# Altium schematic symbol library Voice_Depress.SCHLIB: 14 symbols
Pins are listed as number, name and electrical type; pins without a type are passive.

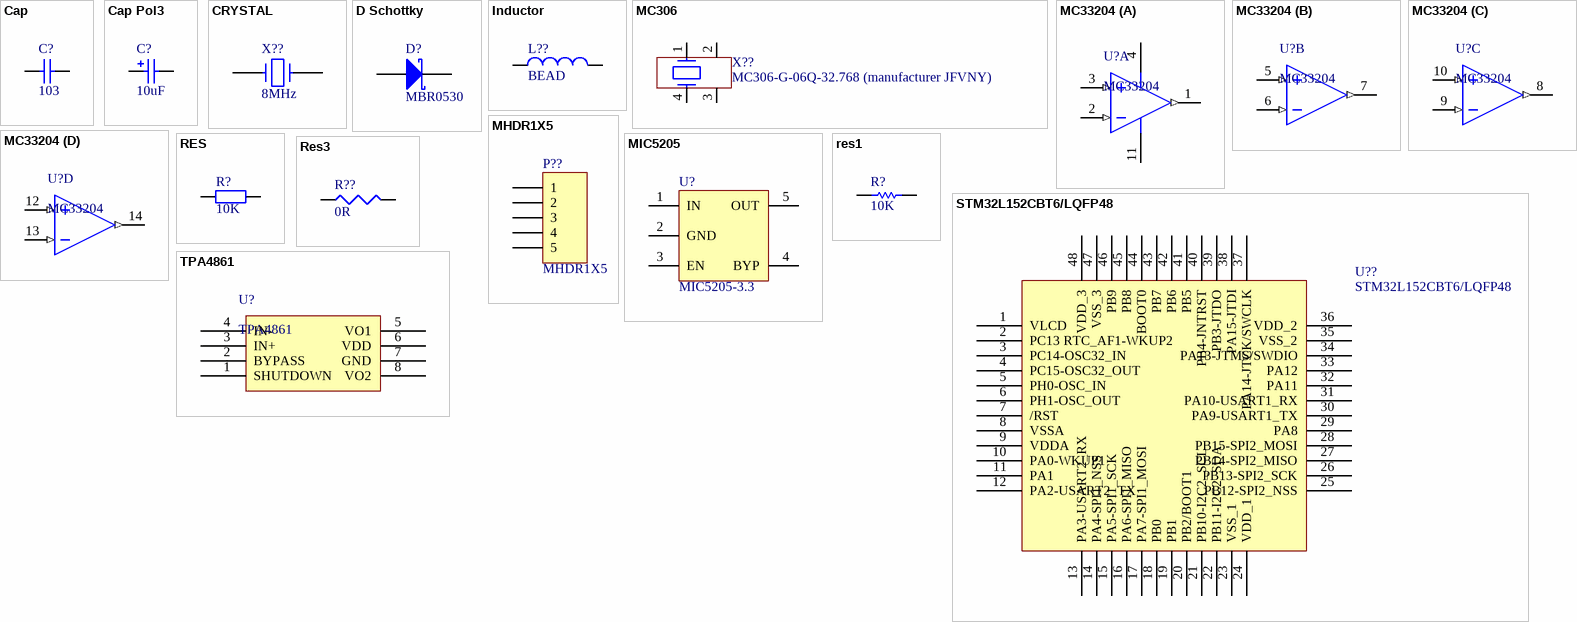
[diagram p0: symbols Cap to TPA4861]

## Cap
designator C?, comment 103
Capacitor
footprint RAD-0.3 (Capacitor; 2 Leads)
footprint CAPR2.54-5.1x3.2 (Capacitor, Ceramic, Thru-Hole, Dipped Radial; Body 5.1 x 3.2 mm (WxT) Pin Spacing 2.54 mm (typ))
footprint CAPR5.08-7.8x3.2 (Capacitor, Ceramic, Thru-Hole, Dipped Radial; Body 7.8 x 3.2 mm (WxT) Pin Spacing 5.08 mm (typ))
simulation model CAP (Capacitor)
signal-integrity model Cap
footprint CR2012-0805
footprint 2012[0805]
footprint CR1608-0603
footprint 1608[0603] (Chip Capacitor; Body 1.6 x 0.8 mm (LxW typ))
footprint R0603
footprint C0603
pins: 1, 2

## Cap Pol3
designator C?, comment 10uF
Polarized Capacitor (Surface Mount); Value: 100pF
simulation model CAP (Capacitor)
footprint 7227
footprint 贴片电容器47u/16V
footprint 3225[1210] (Chip Resistor; Body 3.2 x 2.5 mm (LxW typ))
footprint 6-0805 (Chip Resistor; Body 2.0 x 1.3 mm (LxW typ))
footprint [1608]0603
footprint 6-0805 (Chip Resistor; Body 2.0 x 1.3 mm (LxW typ))
pins: 1, 2
1 alternate drawing of the same symbol

## CRYSTAL
designator X??, comment 8MHz
Crystal
footprint XTAL_socket
pins: 1, 2
2 alternate drawings of the same symbol

## D Schottky
designator D?, comment MBR0530
Schottky Diode
footprint 3216[1206] (Chip Resistor; Body 3.2 x 1.6 mm (LxW typ))
simulation model SKYDIODE (Diode)
signal-integrity model D Schottky
footprint 1608[0603] (Chip Capacitor; Body 1.6 x 0.8 mm (LxW typ))
pins: 1 A, 2 K

## Inductor
designator L??, comment BEAD
Inductor; Code_IEC: 1005; Value: 10mH
footprint 0402-A (Chip Inductor; Body 1 x 0.5 mm (LxW typ))
footprint L0603 (Chip Inductor; Body 1.6 x 0.8 mm (LxW typ))
footprint 2012_Chip (2012 Chip; Chip Inductor; Body 2.0 x 1.2 mm (LxW typ))
footprint 2029 (Chip Inductor; Body 2 x 1.2 mm (LxW typ))
footprint 3261 (3216 Chip; Chip Inductor; Body 3.2 x 1.6 mm (LxW typ))
footprint 4564_Chip (4564 Chip; Chip Inductor; Body 4.5 x 6.4 mm (LxW typ))
simulation model INDUCTOR (Inductor)
signal-integrity model Inductor
pins: 1, 2

## MC306
designator X??, comment MC306-G-06Q-32.768 (manufacturer JFVNY)
footprint SM8 (Footprint not found)
footprint 32.768K-MC146 (XTAL-32.768K)
pins: 1, 2, 3, 4

## MC33204
designator U?
part A pins: 1 OUT1 (out), 2 IN1- (in), 3 IN1+ (in), 4 V+ (power), 11 V- (power)
part B pins: 5 IN1+ (in), 6 IN1- (in), 7 OUT1 (out)
part C pins: 8 OUT1 (out), 9 IN1- (in), 10 IN1+ (in)
part D pins: 12 IN1+ (in), 13 IN1- (in), 14 OUT1 (out)

## MHDR1X5
designator P??
Header, 5-Pin
footprint MHDR1X5 (Connector; Header; 5 Position)
signal-integrity model Connector
pins: 1, 2, 3, 4, 5

## MIC5205
designator U?, comment MIC5205-3.3
800mA Low Dropout Positive Regulator Fixed 2.85V,3V,3.3V and 5V; PackageDocument: revC
footprint SOT23-5 (SOT-23/SC-74A; 5 Leads; Body 3 x 3 mm, inc. leads (LxW max))
footprint DSO-G3 (SOT-223/SC-73; 4 Leads; Body 6.7 x 7.3 mm, inc. leads (LxW max))
footprint SOT23-5 (SOT-23/SC-74A; 5 Leads; Body 3 x 3 mm, inc. leads (LxW max))
footprint SOT23-5 (SOT-23/SC-74A; 5 Leads; Body 3 x 3 mm, inc. leads (LxW max))
pins: 1 IN (power), 2 GND (power), 3 EN (power), 4 BYP (power), 5 OUT (power)

## RES
designator R?, comment 10K
footprint R-0603
footprint R-0805
footprint 1608[0603] (Footprint not found)
footprint 2012[0805]
footprint C0603
footprint R0603
pins: 1, 2

## res1
designator R?, comment 10K
Resistor; Value: 1K
footprint AXIAL-0.3 (Resistor; 2 Leads)
simulation model RESISTOR (Resistor)
signal-integrity model Res
footprint 0603
footprint 1608[0603]
footprint C0603
footprint R0603
pins: 1, 2
1 alternate drawing of the same symbol

## Res3
designator R??, comment 0R
Resistor; Value: 1K
footprint J1-0603 (Chip Resistor; Body 1.6 x 0.8 mm (LxW typ))
footprint 3225[1210] (Chip Resistor; Body 3.2 x 2.5 mm (LxW typ))
footprint 5025[2010] (Chip Resistor; Body 5.0 x 2.5 mm (LxW typ))
footprint 6332[2512] (Chip Resistor; Body 6.3 x 3.2 mm (LxW typ))
simulation model RESISTOR (Resistor)
signal-integrity model Res
pins: 1, 2

## STM32L152CBT6/LQFP48
designator U??
footprint LQFP48
pins: 1 VLCD, 2 PC13 RTC_AF1-WKUP2, 3 PC14-OSC32_IN, 4 PC15-OSC32_OUT, 5 PH0-OSC_IN, 6 PH1-OSC_OUT, 7 /RST, 8 VSSA, 9 VDDA, 10 PA0-WKUP1, 11 PA1, 12 PA2-USART2_TX, 13 PA3-USART2_RX, 14 PA4-SPI1_NSS, 15 PA5-SPI1_SCK, 16 PA6-SPI1_MISO, 17 PA7-SPI1_MOSI, 18 PB0, 19 PB1, 20 PB2/BOOT1, 21 PB10-I2C2_SCL, 22 PB11-I2C2_SDA, 23 VSS_1, 24 VDD_1, 25 PB12-SPI2_NSS, 26 PB13-SPI2_SCK, 27 PB14-SPI2_MISO, 28 PB15-SPI2_MOSI, 29 PA8, 30 PA9-USART1_TX, 31 PA10-USART1_RX, 32 PA11, 33 PA12, 34 PA13-JTMS/SWDIO, 35 VSS_2, 36 VDD_2, 37 PA14-JTCK/SWCLK, 38 PA15-JTDI, 39 PB3-JTDO, 40 PB4-JNTRST, 41 PB5, 42 PB6, 43 PB7, 44 BOOT0, 45 PB8, 46 PB9, 47 VSS_3, 48 VDD_3

## TPA4861
designator U?
1W_AUDIO_AMP
pins: 1 SHUTDOWN, 2 BYPASS, 3 IN+, 4 IN-, 5 VO1, 6 VDD, 7 GND, 8 VO2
